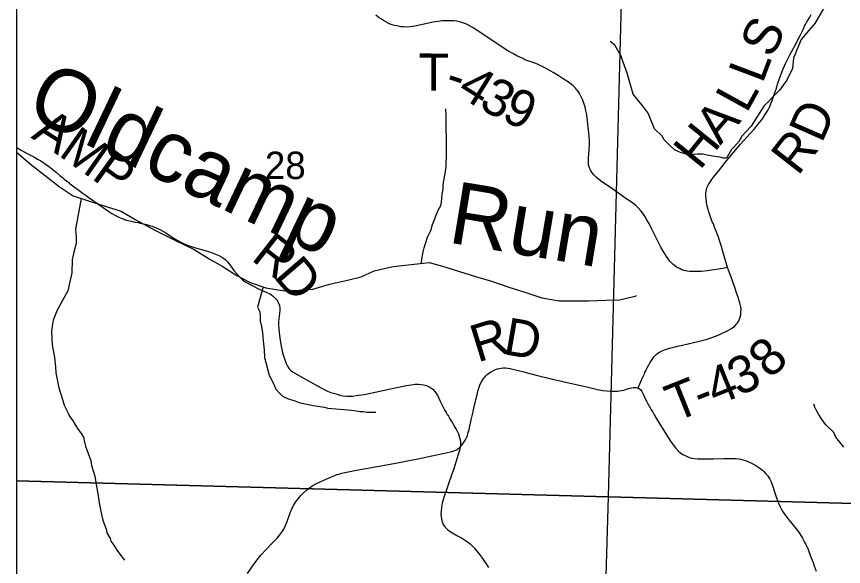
# Model space of a CAD drawing. Extents: x 6.3 to 40.3, y 9 to 31.
# Drawn here: x 8.445 to 9.705, y 28.156 to 28.995 of the extents above; entities that cross this region are included whole.
import ezdxf

# ---------------------------------------------------------------- set-up
doc = ezdxf.new("R2010")
doc.units = 0
for name, color, linetype in [('Default', 7, 'Continuous'), ('GM_X_Corporation', 7, 'Continuous'), ('GM_X_Minor_River', 7, 'Continuous'), ('GM_X_Minor_River_Text', 7, 'Continuous'), ('GM_X_Section', 7, 'Continuous'), ('GM_X_Section_Text', 7, 'Continuous'), ('GM_X_Township_Road', 7, 'Continuous'), ('GM_X_Township_Road_Text', 7, 'Continuous'), ('SH_Cut_Line', 7, 'Continuous'), ('SH_Data', 7, 'Continuous')]:
    doc.layers.add(name, color=color, linetype=linetype)

msp = doc.modelspace()

# ---------------------------------------------------------------- linework, layer by layer
at = {"layer": 'Default'}
msp.add_lwpolyline([(13.1323, 29.9457), (8.4446, 29.9457), (8.4446, 27.9161), (8.9627, 27.9002), (9.9314, 27.8681), (10.145, 27.8635), (10.7129, 27.8423), (11.7175, 27.8106), (12.5872, 27.7766), (13.0625, 27.76), (13.0974, 28.6191), (13.1136, 29.1637), (13.1156, 29.231), (13.116, 29.2473), (13.13, 29.8856)], close=True, dxfattribs=at)
msp.add_lwpolyline([(12.9672, 29.1426), (12.4918, 29.1593), (11.6221, 29.1933), (10.6176, 29.225), (10.0496, 29.2462), (9.8361, 29.2507), (8.8673, 29.2829), (8.4446, 29.2958), (8.4446, 23.1457)], dxfattribs=at)
at = {"layer": 'GM_X_Corporation'}
for points in [[(8.4446, 29.2945), (8.4446, 28.2864), (9.3471, 28.2622), (9.3732, 29.268)], [(8.4446, 28.2864), (8.4446, 27.2958), (9.3175, 27.262), (9.3471, 28.2622)]]:
    msp.add_lwpolyline(points, close=True, dxfattribs=at)
at = {"layer": 'GM_X_Minor_River'}
for points in [[(9.6829, 29.0213), (9.6616, 28.9839), (9.6485, 28.9693), (9.6406, 28.9597), (9.6339, 28.9441), (9.6291, 28.9311), (9.6274, 28.9155), (9.6185, 28.8979), (9.6076, 28.8822), (9.5836, 28.858), (9.5645, 28.8274), (9.5499, 28.8121), (9.545, 28.8033), (9.5345, 28.7918), (9.5267, 28.7788), (9.5221, 28.7787), (9.5168, 28.7802), (9.5054, 28.782), (9.5004, 28.7827), (9.4947, 28.7838), (9.4905, 28.7849), (9.4826, 28.7848), (9.4746, 28.7843), (9.4651, 28.785), (9.4564, 28.7872), (9.4476, 28.7916), (9.4391, 28.7988), (9.4315, 28.8067), (9.4288, 28.8123), (9.4172, 28.8236), (9.4075, 28.8471), (9.3998, 28.8576), (9.3844, 28.8761), (9.3753, 28.9083), (9.3691, 28.9253), (9.3663, 28.9344), (9.3567, 28.951), (9.3494, 28.9566)], [(9.0612, 28.6182), (9.0642, 28.6359), (9.066, 28.642), (9.0711, 28.6584), (9.0763, 28.6684), (9.0785, 28.6775), (9.087, 28.6996), (9.0915, 28.7065), (9.0922, 28.7115), (9.0936, 28.7236), (9.0947, 28.7316), (9.095, 28.7385), (9.0975, 28.7529), (9.0989, 28.7621), (9.0992, 28.767), (9.0998, 28.7853), (9.1001, 28.7925), (9.1, 28.8084), (9.0994, 28.8252), (9.0992, 28.8438), (9.0987, 28.8538)], [(8.4446, 28.7878), (8.4678, 28.7679), (8.489, 28.752), (8.5098, 28.7354), (8.531, 28.7214), (8.5556, 28.7131), (8.5829, 28.7044), (8.6041, 28.698), (8.6256, 28.6852), (8.6563, 28.6682), (8.6858, 28.6535), (8.7154, 28.6395), (8.7384, 28.6251), (8.7581, 28.6138), (8.7805, 28.5998), (8.8005, 28.5892), (8.8247, 28.5809), (8.8528, 28.5764), (8.8755, 28.5772), (8.8963, 28.579), (8.9217, 28.5866), (8.9489, 28.5926), (8.9701, 28.5979), (8.9898, 28.607), (9.0189, 28.6134), (9.0735, 28.6195), (9.0939, 28.6142), (9.1439, 28.5983), (9.1685, 28.5911), (9.195, 28.5821), (9.2196, 28.5741), (9.2453, 28.5658), (9.2718, 28.5613), (9.3169, 28.5613), (9.3434, 28.5621), (9.3638, 28.5624), (9.3876, 28.5681), (9.3895, 28.5692)], [(8.5432, 28.7173), (8.5345, 28.6706), (8.5353, 28.6584), (8.5354, 28.6485), (8.5318, 28.6352), (8.5307, 28.631), (8.5292, 28.6238), (8.5287, 28.604), (8.5229, 28.5766), (8.5065, 28.5471), (8.5006, 28.5315), (8.4988, 28.5224), (8.4977, 28.5144), (8.4991, 28.4942), (8.5027, 28.4745), (8.504, 28.4605), (8.5044, 28.4514), (8.5089, 28.4282), (8.5151, 28.4093), (8.5171, 28.4021), (8.5233, 28.39), (8.5253, 28.3851), (8.5306, 28.3783), (8.5376, 28.3662), (8.543, 28.3587), (8.5465, 28.353), (8.5477, 28.3481), (8.5497, 28.3397), (8.5524, 28.3325), (8.5579, 28.3174), (8.5591, 28.3098), (8.5638, 28.2939), (8.5654, 28.284), (8.569, 28.2639), (8.5703, 28.2533), (8.5743, 28.2355), (8.5759, 28.2268), (8.581, 28.2131), (8.5822, 28.2075), (8.5872, 28.1988), (8.5884, 28.1946), (8.593, 28.1886), (8.598, 28.1806), (8.6038, 28.1727), (8.6092, 28.1656)], [(8.8204, 28.5824), (8.8118, 28.5515), (8.8152, 28.5444), (8.8157, 28.5379), (8.8161, 28.5307), (8.8178, 28.522), (8.8194, 28.5125), (8.8203, 28.5003), (8.8219, 28.4863), (8.8228, 28.4745), (8.8299, 28.448), (8.8369, 28.434), (8.8396, 28.4264), (8.8454, 28.4204), (8.85, 28.4159), (8.8576, 28.4122), (8.8702, 28.4081), (8.8748, 28.4059), (8.8919, 28.4027), (8.8968, 28.4016), (8.914, 28.3987), (8.9189, 28.3976), (8.9372, 28.3959), (8.9436, 28.3952), (8.9493, 28.3949), (8.9554, 28.3942), (8.9626, 28.3935), (8.9679, 28.3925), (8.9733, 28.3921), (8.9778, 28.3914), (8.9869, 28.3911), (8.9923, 28.3912)], [(9.7056, 28.3377), (9.6933, 28.3531), (9.6901, 28.3603), (9.6783, 28.3719), (9.6717, 28.3814), (9.6671, 28.3882), (9.6644, 28.3927), (9.6613, 28.3987), (9.6597, 28.4037)]]:
    msp.add_lwpolyline(points, dxfattribs=at)
at = {"layer": 'GM_X_Section'}
for points in [[(9.3732, 29.268), (10.3703, 29.2306), (10.3378, 28.2352), (9.3471, 28.2622)], [(9.3471, 28.2622), (10.3378, 28.2352), (10.3113, 27.232), (9.3175, 27.262)]]:
    msp.add_lwpolyline(points, close=True, dxfattribs=at)
at = {"layer": 'GM_X_Township_Road'}
for points in [[(9.5284, 28.6117), (9.5212, 28.6106), (9.4974, 28.6069), (9.4887, 28.6061), (9.4809, 28.6056), (9.475, 28.6056), (9.4708, 28.6059), (9.4673, 28.6063), (9.4643, 28.6068), (9.4617, 28.6074), (9.4588, 28.6084), (9.4562, 28.6097), (9.4532, 28.6112), (9.4507, 28.6127), (9.4475, 28.6148), (9.4456, 28.6164), (9.4432, 28.6186), (9.4406, 28.6214), (9.4377, 28.625), (9.4351, 28.6286), (9.4295, 28.638), (9.4267, 28.6428), (9.4193, 28.6572), (9.4124, 28.6716), (9.4092, 28.6779), (9.4055, 28.6849), (9.4025, 28.6902), (9.3994, 28.6947), (9.3963, 28.6986), (9.392, 28.7031), (9.3884, 28.7065), (9.384, 28.71), (9.3789, 28.7135), (9.3733, 28.7173), (9.3644, 28.7237), (9.3569, 28.7289), (9.3469, 28.7358), (9.3368, 28.7427), (9.3319, 28.7463), (9.3282, 28.7496), (9.3262, 28.7516), (9.3244, 28.7534), (9.3224, 28.7558), (9.3211, 28.7576), (9.32, 28.7595), (9.3187, 28.7619), (9.3179, 28.7639), (9.3171, 28.7668), (9.3166, 28.7687), (9.3163, 28.7718), (9.3162, 28.7748), (9.3162, 28.7786), (9.3167, 28.7848), (9.3173, 28.791), (9.3178, 28.8003), (9.3177, 28.8052), (9.3173, 28.8129), (9.316, 28.8261), (9.3142, 28.8408), (9.3132, 28.8472), (9.312, 28.8535), (9.3111, 28.8572), (9.3095, 28.8625), (9.308, 28.8669), (9.3059, 28.8714), (9.3043, 28.8745), (9.3027, 28.8774), (9.301, 28.8798), (9.2993, 28.8823), (9.2981, 28.8836), (9.2967, 28.8853), (9.2951, 28.887), (9.293, 28.889), (9.2906, 28.8911), (9.2873, 28.8934), (9.278, 28.8998), (9.27, 28.905), (9.2626, 28.9095), (9.2554, 28.9135), (9.2496, 28.9166), (9.2436, 28.9196), (9.2386, 28.9218), (9.2304, 28.925), (9.2239, 28.9273), (9.2196, 28.9289), (9.2161, 28.9305), (9.2118, 28.9325), (9.207, 28.9349), (9.2009, 28.9381), (9.1934, 28.9425), (9.1785, 28.952), (9.1568, 28.9666), (9.1468, 28.9736), (9.1417, 28.9769), (9.137, 28.9796), (9.1326, 28.982), (9.1293, 28.9836), (9.1265, 28.9847), (9.1233, 28.9857), (9.1192, 28.9868), (9.115, 28.9875), (9.1109, 28.9879), (9.1056, 28.9882), (9.1002, 28.9883), (9.0933, 28.9881), (9.087, 28.9872), (9.0797, 28.9859), (9.0636, 28.9823), (9.0519, 28.9798), (9.0445, 28.9789), (9.0389, 28.9787), (9.0342, 28.9788), (9.0306, 28.9792), (9.0268, 28.9798), (9.0236, 28.9805), (9.0207, 28.9812), (9.0173, 28.9822), (9.0143, 28.9833), (9.0111, 28.9847), (9.0075, 28.9867), (9.0039, 28.9888), (9.0009, 28.9906), (8.9975, 28.9928), (8.9923, 28.9966)], [(9.5284, 28.6117), (9.526, 28.6189), (9.5212, 28.6362), (9.5184, 28.6457), (9.5166, 28.6516), (9.5138, 28.6599), (9.5096, 28.6709), (9.5079, 28.6749), (9.5067, 28.6784), (9.5051, 28.6817), (9.5034, 28.6863), (9.5022, 28.6892), (9.5011, 28.6927), (9.4998, 28.6962), (9.4986, 28.7004), (9.4976, 28.7039), (9.4967, 28.7075), (9.496, 28.7118), (9.4955, 28.7173), (9.4953, 28.7206), (9.4953, 28.7234), (9.4954, 28.7256), (9.4957, 28.7281), (9.4962, 28.7308), (9.497, 28.7332), (9.498, 28.7357), (9.4993, 28.7384), (9.5006, 28.7406), (9.5022, 28.7432), (9.5066, 28.7491), (9.5143, 28.7589), (9.5269, 28.7748), (9.5373, 28.7875), (9.548, 28.7999), (9.563, 28.8164), (9.5687, 28.8228), (9.575, 28.8303), (9.5797, 28.8363), (9.5824, 28.8401), (9.5848, 28.8436), (9.5878, 28.8483), (9.5902, 28.8524), (9.5923, 28.8567), (9.595, 28.863), (9.5964, 28.8664), (9.5996, 28.8758), (9.6005, 28.8788), (9.6023, 28.8841), (9.6051, 28.8929), (9.6072, 28.8988), (9.6112, 28.9099), (9.6133, 28.9151), (9.6174, 28.9241), (9.6235, 28.9363), (9.6308, 28.95), (9.6328, 28.9538), (9.6371, 28.9621), (9.6393, 28.9666), (9.6415, 28.971), (9.6434, 28.9749), (9.6458, 28.9799), (9.6472, 28.9827), (9.6493, 28.9864), (9.651, 28.9897), (9.6535, 28.9938), (9.6559, 28.9976)], [(8.4446, 28.7952), (8.4449, 28.7951), (8.4518, 28.791), (8.461, 28.786), (8.4708, 28.7808), (8.4767, 28.7774), (8.4814, 28.7745), (8.4866, 28.7711), (8.4932, 28.7664), (8.4997, 28.7615), (8.5055, 28.7569), (8.5106, 28.7525), (8.5147, 28.749), (8.5155, 28.7483), (8.5163, 28.7475), (8.5174, 28.7467), (8.5206, 28.7442), (8.5227, 28.7425), (8.5242, 28.7414), (8.5255, 28.7403), (8.5269, 28.7392), (8.5278, 28.7386), (8.5311, 28.736), (8.533, 28.7345), (8.534, 28.7338), (8.5364, 28.732), (8.5379, 28.7309), (8.5399, 28.7295), (8.5419, 28.7281), (8.5464, 28.7248), (8.5505, 28.722), (8.5555, 28.7184), (8.5619, 28.7137), (8.5678, 28.7095), (8.5721, 28.7065), (8.5764, 28.7035), (8.584, 28.6983), (8.5898, 28.6944), (8.5954, 28.6911), (8.6003, 28.6887), (8.6054, 28.6865), (8.6088, 28.6853), (8.6142, 28.6837), (8.6196, 28.6825), (8.6251, 28.6813), (8.6299, 28.6804), (8.6328, 28.6798), (8.6374, 28.6788), (8.6407, 28.678), (8.6449, 28.6769), (8.6472, 28.6762), (8.649, 28.6756), (8.6514, 28.6748), (8.6525, 28.6743), (8.6551, 28.6735), (8.6565, 28.673), (8.663, 28.6698), (8.6684, 28.6668), (8.6705, 28.6656), (8.6726, 28.6642), (8.6752, 28.6626), (8.682, 28.6581), (8.6883, 28.6541), (8.6948, 28.6505), (8.7009, 28.6477), (8.709, 28.6446), (8.7172, 28.642), (8.7321, 28.6377), (8.7386, 28.6358), (8.7444, 28.6336), (8.7542, 28.6297), (8.7585, 28.6273), (8.7624, 28.6243), (8.7659, 28.6208), (8.7701, 28.6153), (8.776, 28.6073), (8.7803, 28.6021), (8.7846, 28.5975), (8.7887, 28.5937), (8.7931, 28.5903), (8.8037, 28.5846), (8.8143, 28.5789), (8.82, 28.5766), (8.8263, 28.5739), (8.8307, 28.5716), (8.8334, 28.5701), (8.8368, 28.5673), (8.8399, 28.5643), (8.8411, 28.5629), (8.8436, 28.5586), (8.8452, 28.5539), (8.8457, 28.5502), (8.8458, 28.5471), (8.8454, 28.5416), (8.8444, 28.5337), (8.844, 28.5294), (8.8439, 28.5245), (8.8442, 28.5184), (8.8454, 28.5081), (8.8469, 28.4978), (8.8484, 28.4894), (8.8502, 28.4817), (8.8525, 28.4742), (8.8555, 28.4656), (8.8576, 28.4613), (8.8603, 28.4574), (8.8633, 28.4544), (8.8651, 28.453), (8.8686, 28.4507), (8.8878, 28.4401), (8.9091, 28.4283), (8.9144, 28.4255), (8.9188, 28.4235), (8.9239, 28.4215), (8.9297, 28.4197), (8.9332, 28.4187), (8.9372, 28.4175), (8.9419, 28.4164), (8.9473, 28.4157), (8.9521, 28.4156), (8.9569, 28.4159), (8.9624, 28.4165), (8.9661, 28.4171), (8.9704, 28.4176), (8.9746, 28.4183), (8.9795, 28.4193), (9.0146, 28.4267), (9.0391, 28.4319), (9.0463, 28.4332), (9.0524, 28.434), (9.0572, 28.4341), (9.0614, 28.4337), (9.0656, 28.433), (9.0696, 28.4318), (9.0735, 28.4301), (9.076, 28.4286), (9.0789, 28.4264), (9.0823, 28.4229), (9.0847, 28.4194), (9.0865, 28.4162), (9.0898, 28.409), (9.0921, 28.4041), (9.0932, 28.402), (9.0959, 28.3967), (9.0973, 28.3941), (9.0985, 28.3921), (9.0997, 28.39), (9.1009, 28.388), (9.1019, 28.3865), (9.1028, 28.385), (9.105, 28.3814), (9.1067, 28.3788), (9.1089, 28.3751), (9.1128, 28.3687), (9.1157, 28.3633), (9.118, 28.3582), (9.1198, 28.3529), (9.1213, 28.3469), (9.1215, 28.344), (9.1214, 28.3415), (9.1209, 28.3387)], [(9.3916, 28.428), (9.3936, 28.4322), (9.3979, 28.4417), (9.3996, 28.4456), (9.4006, 28.4478), (9.4017, 28.45), (9.4025, 28.4517), (9.4038, 28.4545), (9.4048, 28.4567), (9.4059, 28.4589), (9.4082, 28.4633), (9.4094, 28.4654), (9.41, 28.4664), (9.4112, 28.4685), (9.4133, 28.4716), (9.4162, 28.4756), (9.417, 28.4766), (9.4196, 28.4792), (9.4219, 28.4812), (9.4245, 28.4829), (9.4278, 28.4846), (9.4324, 28.4864), (9.4401, 28.4888), (9.4485, 28.491), (9.4539, 28.4923), (9.4575, 28.4931), (9.4617, 28.494), (9.4849, 28.4995), (9.4957, 28.5024), (9.5061, 28.5056), (9.5101, 28.5072), (9.514, 28.509), (9.518, 28.5107), (9.5213, 28.5123), (9.5259, 28.5144), (9.5298, 28.5165), (9.5334, 28.5185), (9.5363, 28.5204), (9.5387, 28.5222), (9.5409, 28.5243), (9.5427, 28.5263), (9.5438, 28.5282), (9.5453, 28.5308), (9.5466, 28.5336), (9.5475, 28.536), (9.5484, 28.5396), (9.5488, 28.5433), (9.5489, 28.5476), (9.5484, 28.5519), (9.547, 28.558), (9.5462, 28.561), (9.5448, 28.5651), (9.5427, 28.5716), (9.5393, 28.5816), (9.5332, 28.5985), (9.5297, 28.6078), (9.5284, 28.6117)], [(9.1209, 28.3387), (9.1232, 28.3409), (9.1244, 28.3423), (9.1256, 28.344), (9.127, 28.346), (9.1289, 28.3492), (9.1302, 28.352), (9.1318, 28.3558), (9.1332, 28.3601), (9.1344, 28.3648), (9.1376, 28.3794), (9.1395, 28.3879), (9.1421, 28.3996), (9.1466, 28.4182), (9.1484, 28.425), (9.1496, 28.4293), (9.1515, 28.4341), (9.1532, 28.4374), (9.1548, 28.4402), (9.1564, 28.4425), (9.1579, 28.4444), (9.16, 28.4466), (9.1621, 28.4486), (9.164, 28.4504), (9.166, 28.4519), (9.1685, 28.4535), (9.1714, 28.4551), (9.1744, 28.4564), (9.1776, 28.4574), (9.1805, 28.4581), (9.1833, 28.4585), (9.1865, 28.4587), (9.1898, 28.4587), (9.1932, 28.4584), (9.1972, 28.4577), (9.2177, 28.4526), (9.2231, 28.4513), (9.2291, 28.4497), (9.2388, 28.4473), (9.2617, 28.4417), (9.2774, 28.4381), (9.2931, 28.4344), (9.3045, 28.432), (9.3067, 28.4315), (9.314, 28.4298), (9.3303, 28.4261), (9.3382, 28.4246), (9.3438, 28.4238), (9.35, 28.4234), (9.3555, 28.4233), (9.3605, 28.4236), (9.3666, 28.4244), (9.3702, 28.4251), (9.3744, 28.4262), (9.3792, 28.4277), (9.3822, 28.4286), (9.3852, 28.429), (9.3883, 28.429), (9.3906, 28.4284), (9.3916, 28.428)], [(9.3916, 28.428), (9.3924, 28.4278), (9.394, 28.4268), (9.3954, 28.4257), (9.3966, 28.4243), (9.3976, 28.4228), (9.3981, 28.4217), (9.3986, 28.4208), (9.4, 28.4178), (9.4035, 28.4106), (9.4046, 28.4083), (9.4057, 28.4063), (9.4062, 28.4052), (9.4082, 28.4015), (9.4094, 28.3994), (9.4103, 28.398), (9.4109, 28.3969), (9.4121, 28.3947), (9.4137, 28.3921), (9.4143, 28.3911), (9.4165, 28.3873), (9.4226, 28.3773), (9.4262, 28.3714), (9.4301, 28.3651), (9.4327, 28.3609), (9.4413, 28.3472), (9.4452, 28.3415), (9.449, 28.3367), (9.4529, 28.3326), (9.4567, 28.3294), (9.4603, 28.3269), (9.4635, 28.3251), (9.4666, 28.3237), (9.4699, 28.3223), (9.4732, 28.3214), (9.4774, 28.3207), (9.4823, 28.3202), (9.4945, 28.3201), (9.5068, 28.3202), (9.5229, 28.3207), (9.5334, 28.3207), (9.5403, 28.3205), (9.5454, 28.3201), (9.5483, 28.3197), (9.5518, 28.3187), (9.5555, 28.3175), (9.5594, 28.3159), (9.5627, 28.3145), (9.5667, 28.3126), (9.5713, 28.31), (9.576, 28.3071), (9.5792, 28.3047), (9.5816, 28.3027), (9.5839, 28.3005), (9.5864, 28.2978), (9.5891, 28.2946), (9.5911, 28.2916), (9.5927, 28.2889), (9.5949, 28.285), (9.5977, 28.2765), (9.5999, 28.27), (9.6029, 28.2606), (9.606, 28.2526), (9.6086, 28.2469), (9.6113, 28.242), (9.6138, 28.2377), (9.617, 28.2332), (9.6219, 28.2269), (9.6328, 28.2135), (9.6364, 28.2086), (9.6385, 28.2056), (9.6424, 28.1992), (9.6457, 28.1933), (9.6471, 28.1905), (9.6505, 28.1832), (9.655, 28.1717), (9.6587, 28.1619), (9.6606, 28.1569), (9.6636, 28.1489)], [(8.7964, 28.1454), (8.8068, 28.1601), (8.8128, 28.168), (8.8176, 28.1737), (8.8252, 28.1819), (8.8334, 28.1904), (8.842, 28.1994), (8.846, 28.2042), (8.8489, 28.2082), (8.8518, 28.213), (8.8546, 28.2185), (8.8573, 28.2248), (8.8618, 28.2377), (8.8643, 28.244), (8.8655, 28.2466), (8.8668, 28.249), (8.87, 28.2543), (8.8738, 28.2593), (8.8778, 28.264), (8.8827, 28.2688), (8.8873, 28.273), (8.8912, 28.276), (8.8954, 28.2788), (8.9007, 28.2819), (8.9085, 28.2858), (8.9221, 28.2919), (8.9296, 28.2949), (8.933, 28.2961), (8.9361, 28.297), (8.9404, 28.2981), (8.9451, 28.2992), (8.9524, 28.3008), (8.9597, 28.3022), (9.0001, 28.3093), (9.0251, 28.3142), (9.0428, 28.3177), (9.0564, 28.3204), (9.0848, 28.3261), (9.0969, 28.3287), (9.106, 28.3306), (9.108, 28.3311), (9.1096, 28.3316), (9.1112, 28.3322), (9.1125, 28.3328), (9.1136, 28.3333), (9.115, 28.334), (9.1165, 28.3349), (9.1176, 28.3357), (9.1191, 28.337), (9.1209, 28.3387)], [(9.1209, 28.3387), (9.1203, 28.335), (9.1193, 28.3316), (9.1104, 28.3036), (9.1093, 28.3), (9.0953, 28.2599), (9.0934, 28.2526), (9.0922, 28.2464), (9.0916, 28.2409), (9.0915, 28.236), (9.0916, 28.2324), (9.0928, 28.2258), (9.0937, 28.2229), (9.095, 28.2202), (9.0973, 28.2166), (9.0984, 28.2152), (9.1014, 28.2122), (9.1039, 28.2103), (9.108, 28.2076), (9.1157, 28.2034), (9.1228, 28.1996), (9.1275, 28.1966), (9.1319, 28.1934), (9.1358, 28.1904), (9.1395, 28.1871), (9.1412, 28.1854), (9.1429, 28.1836), (9.144, 28.1821), (9.1464, 28.1794), (9.1506, 28.174), (9.152, 28.172), (9.1535, 28.17), (9.1595, 28.1613), (9.1639, 28.1545)]]:
    msp.add_lwpolyline(points, dxfattribs=at)
at = {"layer": 'SH_Cut_Line'}
msp.add_lwpolyline([(12.9672, 29.1426), (12.4918, 29.1593), (11.6221, 29.1933), (10.6176, 29.225), (10.0496, 29.2462), (9.8361, 29.2507), (8.8673, 29.2829), (8.4446, 29.2958), (8.4446, 23.1457)], dxfattribs=at)
at = {"layer": 'SH_Data'}
msp.add_line((8.4446, 29.9457), (8.4446, 23.1457), dxfattribs=at)

# ---------------------------------------------------------------- texts
at = {"layer": 'GM_X_Minor_River_Text'}
for s, height, rotation, p in [('Oldcamp', 0.0947, 334.5935, (8.4553, 28.8446)), ('Run', 0.09469, 350.6031, (9.1004, 28.6504))]:
    msp.add_text(s, height=height, rotation=rotation, dxfattribs=at).set_placement(p)
at = {"layer": 'GM_X_Section_Text'}
msp.add_text('28', height=0.04186, rotation=0, dxfattribs=at).set_placement((8.8231, 28.7468))
at = {"layer": 'GM_X_Township_Road_Text'}
for s, rotation, p in [('S', 63.9896, (9.596, 28.9296)), ('T', 359.7686, (9.0572, 28.8816)), ('L', 69.2737, (9.5815, 28.8912)), ('-', 341.6317, (9.095, 28.8822)), ('4', 328.0277, (9.1139, 28.8763)), ('3', 331.9036, (9.1472, 28.8557)), ('9', 335.7712, (9.1818, 28.8374)), ('L', 61.1458, (9.5573, 28.846)), ('D', 66.3257, (9.672, 28.8003)), ('A', 49.1664, (9.5172, 28.7975)), ('A', 327.393, (8.4654, 28.8101)), ('M', 324.9238, (8.507, 28.7835)), ('H', 51.0023, (9.486, 28.759)), ('R', 52.0387, (9.6355, 28.7504)), ('P', 324.0862, (8.5573, 28.7482)), ('R', 321.8717, (8.8006, 28.6244)), ('D', 310.723, (8.8352, 28.5976)), ('R', 17.1561, (9.1472, 28.4668)), ('D', 350.2526, (9.1849, 28.4801)), ('8', 43.2685, (9.5932, 28.4408)), ('3', 25.2024, (9.5454, 28.415)), ('4', 21.972, (9.5098, 28.4005)), ('T', 21.7218, (9.4484, 28.376)), ('-', 21.7646, (9.4879, 28.3917))]:
    msp.add_text(s, height=0.0568, rotation=rotation, dxfattribs=at).set_placement(p)

doc.saveas('drawing.dxf')
